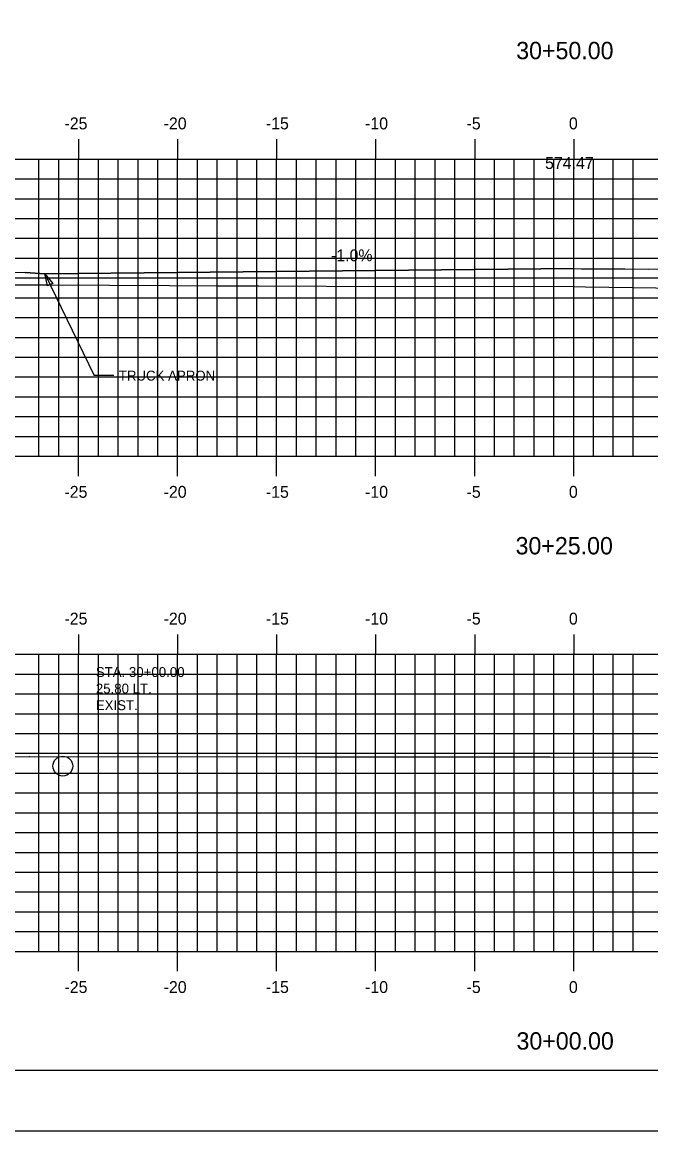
# Model space of a CAD drawing. Extents: x 1048109 to 1048279, y 781630 to 781740.
# Drawn here: x 1048163.9 to 1048195.6, y 781630.1 to 781686.1 of the extents above; entities that cross this region are included whole.
import ezdxf

# ---------------------------------------------------------------- set-up
doc = ezdxf.new("R2010")
doc.units = 0
for name, color, linetype in [('ANNOTATION', 7, 'Continuous'), ('D_Roadway_Centerline', 7, 'Continuous'), ('D_Roadway_Centerline_Text', 7, 'Continuous'), ('D_Text_Monospaced', 7, 'Continuous'), ('Default', 7, 'Continuous'), ('H_V ANNOTATION', 7, 'Continuous'), ('MAJOR', 7, 'Continuous'), ('MINOR', 7, 'Continuous'), ('S_Roadway_Centerline', 7, 'Continuous'), ('S_Utilities_UG_Water_Line', 7, 'Continuous')]:
    doc.layers.add(name, color=color, linetype=linetype)

msp = doc.modelspace()

# ---------------------------------------------------------------- linework, layer by layer
at = {"layer": 'ANNOTATION'}
for p in [(1048165.033, 781673.396), (1048168.514, 781668.263)]:
    msp.add_line(p, (1048167.514, 781668.263), dxfattribs=at)
msp.add_lwpolyline([(1048165.159, 781672.791), (1048165.033, 781673.396), (1048165.429, 781672.921)], close=True, dxfattribs=at)
at = {"layer": 'D_Roadway_Centerline'}
for p, q in [((1048145.246, 781673.605), (1048164.033, 781673.476)), ((1048165.033, 781673.396), (1048164.033, 781673.476)), ((1048191.733, 781673.663), (1048165.033, 781673.396)), ((1048191.733, 781673.663), (1048222.163, 781673.508))]:
    msp.add_line(p, q, dxfattribs=at)
msp.add_lwpolyline([(1048164.033, 781673.476), (1048165.033, 781673.396), (1048191.733, 781673.663), (1048192.119, 781673.655), (1048195.523, 781673.644)], dxfattribs=at)
at = {"layer": 'Default'}
msp.add_line((1048116.734, 781633.195), (1048276.734, 781633.195), dxfattribs=at)
msp.add_lwpolyline([(1048108.64, 781630.136), (1048278.64, 781630.136), (1048278.64, 781740.136), (1048108.64, 781740.136)], close=True, dxfattribs=at)
at = {"layer": 'MAJOR'}
for p, q in [((1048166.733, 781680.197), (1048166.733, 781679.195)), ((1048166.733, 781680.197), (1048166.733, 781679.195)), ((1048171.733, 781680.197), (1048171.733, 781679.195)), ((1048171.733, 781680.197), (1048171.733, 781679.195)), ((1048176.733, 781680.197), (1048176.733, 781679.195)), ((1048176.733, 781680.197), (1048176.733, 781679.195)), ((1048181.733, 781680.197), (1048181.733, 781679.195)), ((1048181.733, 781680.197), (1048181.733, 781679.195)), ((1048186.733, 781680.197), (1048186.733, 781679.195)), ((1048186.733, 781680.197), (1048186.733, 781679.195)), ((1048191.733, 781680.197), (1048191.733, 781679.195)), ((1048191.733, 781680.197), (1048191.733, 781679.195)), ((1048121.733, 781679.195), (1048261.733, 781679.195)), ((1048121.733, 781679.195), (1048261.733, 781679.195)), ((1048121.733, 781679.195), (1048261.733, 781679.195)), ((1048121.733, 781679.195), (1048261.733, 781679.195)), ((1048166.733, 781664.195), (1048166.733, 781679.195)), ((1048166.733, 781664.195), (1048166.733, 781679.195)), ((1048171.733, 781664.195), (1048171.733, 781679.195)), ((1048171.733, 781664.195), (1048171.733, 781679.195)), ((1048176.733, 781664.195), (1048176.733, 781679.195)), ((1048176.733, 781664.195), (1048176.733, 781679.195)), ((1048181.733, 781664.195), (1048181.733, 781679.195)), ((1048181.733, 781664.195), (1048181.733, 781679.195)), ((1048186.733, 781664.195), (1048186.733, 781679.195)), ((1048186.733, 781664.195), (1048186.733, 781679.195)), ((1048191.733, 781664.195), (1048191.733, 781679.195)), ((1048191.733, 781664.195), (1048191.733, 781679.195)), ((1048121.733, 781674.195), (1048261.733, 781674.195)), ((1048121.733, 781674.195), (1048261.733, 781674.195)), ((1048121.733, 781669.195), (1048261.733, 781669.195)), ((1048121.733, 781669.195), (1048261.733, 781669.195)), ((1048121.733, 781664.195), (1048261.733, 781664.195)), ((1048121.733, 781664.195), (1048261.733, 781664.195)), ((1048121.733, 781664.195), (1048261.733, 781664.195)), ((1048121.733, 781664.195), (1048261.733, 781664.195)), ((1048166.733, 781663.193), (1048166.733, 781664.195)), ((1048166.733, 781663.193), (1048166.733, 781664.195)), ((1048171.733, 781663.193), (1048171.733, 781664.195)), ((1048171.733, 781663.193), (1048171.733, 781664.195)), ((1048176.733, 781663.193), (1048176.733, 781664.195)), ((1048176.733, 781663.193), (1048176.733, 781664.195)), ((1048181.733, 781663.193), (1048181.733, 781664.195)), ((1048181.733, 781663.193), (1048181.733, 781664.195)), ((1048186.733, 781663.193), (1048186.733, 781664.195)), ((1048186.733, 781663.193), (1048186.733, 781664.195)), ((1048191.733, 781663.193), (1048191.733, 781664.195)), ((1048191.733, 781663.193), (1048191.733, 781664.195)), ((1048166.733, 781655.197), (1048166.733, 781654.195)), ((1048166.733, 781655.197), (1048166.733, 781654.195)), ((1048171.733, 781655.197), (1048171.733, 781654.195)), ((1048171.733, 781655.197), (1048171.733, 781654.195)), ((1048176.733, 781655.197), (1048176.733, 781654.195)), ((1048176.733, 781655.197), (1048176.733, 781654.195)), ((1048181.733, 781655.197), (1048181.733, 781654.195)), ((1048181.733, 781655.197), (1048181.733, 781654.195)), ((1048186.733, 781655.197), (1048186.733, 781654.195)), ((1048186.733, 781655.197), (1048186.733, 781654.195)), ((1048191.733, 781655.197), (1048191.733, 781654.195)), ((1048191.733, 781655.197), (1048191.733, 781654.195)), ((1048121.733, 781654.195), (1048261.733, 781654.195)), ((1048121.733, 781654.195), (1048261.733, 781654.195)), ((1048121.733, 781654.195), (1048261.733, 781654.195)), ((1048121.733, 781654.195), (1048261.733, 781654.195)), ((1048166.733, 781639.195), (1048166.733, 781654.195)), ((1048166.733, 781639.195), (1048166.733, 781654.195)), ((1048171.733, 781639.195), (1048171.733, 781654.195)), ((1048171.733, 781639.195), (1048171.733, 781654.195)), ((1048176.733, 781639.195), (1048176.733, 781654.195)), ((1048176.733, 781639.195), (1048176.733, 781654.195)), ((1048181.733, 781639.195), (1048181.733, 781654.195)), ((1048181.733, 781639.195), (1048181.733, 781654.195)), ((1048186.733, 781639.195), (1048186.733, 781654.195)), ((1048186.733, 781639.195), (1048186.733, 781654.195)), ((1048191.733, 781639.195), (1048191.733, 781654.195)), ((1048191.733, 781639.195), (1048191.733, 781654.195)), ((1048121.733, 781649.195), (1048261.733, 781649.195)), ((1048121.733, 781649.195), (1048261.733, 781649.195)), ((1048121.733, 781644.195), (1048261.733, 781644.195)), ((1048121.733, 781644.195), (1048261.733, 781644.195)), ((1048121.733, 781639.195), (1048261.733, 781639.195)), ((1048121.733, 781639.195), (1048261.733, 781639.195)), ((1048121.733, 781639.195), (1048261.733, 781639.195)), ((1048121.733, 781639.195), (1048261.733, 781639.195)), ((1048166.733, 781638.193), (1048166.733, 781639.195)), ((1048166.733, 781638.193), (1048166.733, 781639.195)), ((1048171.733, 781638.193), (1048171.733, 781639.195)), ((1048171.733, 781638.193), (1048171.733, 781639.195)), ((1048176.733, 781638.193), (1048176.733, 781639.195)), ((1048176.733, 781638.193), (1048176.733, 781639.195)), ((1048181.733, 781638.193), (1048181.733, 781639.195)), ((1048181.733, 781638.193), (1048181.733, 781639.195)), ((1048186.733, 781638.193), (1048186.733, 781639.195)), ((1048186.733, 781638.193), (1048186.733, 781639.195)), ((1048191.733, 781638.193), (1048191.733, 781639.195)), ((1048191.733, 781638.193), (1048191.733, 781639.195))]:
    msp.add_line(p, q, dxfattribs=at)
at = {"layer": 'MINOR'}
for p, q in [((1048164.733, 781664.195), (1048164.733, 781679.195)), ((1048164.733, 781664.195), (1048164.733, 781679.195)), ((1048165.733, 781664.195), (1048165.733, 781679.195)), ((1048165.733, 781664.195), (1048165.733, 781679.195)), ((1048167.733, 781664.195), (1048167.733, 781679.195)), ((1048167.733, 781664.195), (1048167.733, 781679.195)), ((1048168.733, 781664.195), (1048168.733, 781679.195)), ((1048168.733, 781664.195), (1048168.733, 781679.195)), ((1048169.733, 781664.195), (1048169.733, 781679.195)), ((1048169.733, 781664.195), (1048169.733, 781679.195)), ((1048170.733, 781664.195), (1048170.733, 781679.195)), ((1048170.733, 781664.195), (1048170.733, 781679.195)), ((1048172.733, 781664.195), (1048172.733, 781679.195)), ((1048172.733, 781664.195), (1048172.733, 781679.195)), ((1048173.733, 781664.195), (1048173.733, 781679.195)), ((1048173.733, 781664.195), (1048173.733, 781679.195)), ((1048174.733, 781664.195), (1048174.733, 781679.195)), ((1048174.733, 781664.195), (1048174.733, 781679.195)), ((1048175.733, 781664.195), (1048175.733, 781679.195)), ((1048175.733, 781664.195), (1048175.733, 781679.195)), ((1048177.733, 781664.195), (1048177.733, 781679.195)), ((1048177.733, 781664.195), (1048177.733, 781679.195)), ((1048178.733, 781664.195), (1048178.733, 781679.195)), ((1048178.733, 781664.195), (1048178.733, 781679.195)), ((1048179.733, 781664.195), (1048179.733, 781679.195)), ((1048179.733, 781664.195), (1048179.733, 781679.195)), ((1048180.733, 781664.195), (1048180.733, 781679.195)), ((1048180.733, 781664.195), (1048180.733, 781679.195)), ((1048182.733, 781664.195), (1048182.733, 781679.195)), ((1048182.733, 781664.195), (1048182.733, 781679.195)), ((1048183.733, 781664.195), (1048183.733, 781679.195)), ((1048183.733, 781664.195), (1048183.733, 781679.195)), ((1048184.733, 781664.195), (1048184.733, 781679.195)), ((1048184.733, 781664.195), (1048184.733, 781679.195)), ((1048185.733, 781664.195), (1048185.733, 781679.195)), ((1048185.733, 781664.195), (1048185.733, 781679.195)), ((1048187.733, 781664.195), (1048187.733, 781679.195)), ((1048187.733, 781664.195), (1048187.733, 781679.195)), ((1048188.733, 781664.195), (1048188.733, 781679.195)), ((1048188.733, 781664.195), (1048188.733, 781679.195)), ((1048189.733, 781664.195), (1048189.733, 781679.195)), ((1048189.733, 781664.195), (1048189.733, 781679.195)), ((1048190.733, 781664.195), (1048190.733, 781679.195)), ((1048190.733, 781664.195), (1048190.733, 781679.195)), ((1048192.733, 781664.195), (1048192.733, 781679.195)), ((1048192.733, 781664.195), (1048192.733, 781679.195)), ((1048193.733, 781664.195), (1048193.733, 781679.195)), ((1048193.733, 781664.195), (1048193.733, 781679.195)), ((1048194.733, 781664.195), (1048194.733, 781679.195)), ((1048194.733, 781664.195), (1048194.733, 781679.195)), ((1048121.733, 781678.195), (1048261.733, 781678.195)), ((1048121.733, 781678.195), (1048261.733, 781678.195)), ((1048121.733, 781677.195), (1048261.733, 781677.195)), ((1048121.733, 781677.195), (1048261.733, 781677.195)), ((1048121.733, 781676.195), (1048261.733, 781676.195)), ((1048121.733, 781676.195), (1048261.733, 781676.195)), ((1048121.733, 781675.195), (1048261.733, 781675.195)), ((1048121.733, 781675.195), (1048261.733, 781675.195)), ((1048121.733, 781673.195), (1048261.733, 781673.195)), ((1048121.733, 781673.195), (1048261.733, 781673.195)), ((1048121.733, 781672.195), (1048261.733, 781672.195)), ((1048121.733, 781672.195), (1048261.733, 781672.195)), ((1048121.733, 781671.195), (1048261.733, 781671.195)), ((1048121.733, 781671.195), (1048261.733, 781671.195)), ((1048121.733, 781670.195), (1048261.733, 781670.195)), ((1048121.733, 781670.195), (1048261.733, 781670.195)), ((1048121.733, 781668.195), (1048261.733, 781668.195)), ((1048121.733, 781668.195), (1048261.733, 781668.195)), ((1048121.733, 781667.195), (1048261.733, 781667.195)), ((1048121.733, 781667.195), (1048261.733, 781667.195)), ((1048121.733, 781666.195), (1048261.733, 781666.195)), ((1048121.733, 781666.195), (1048261.733, 781666.195)), ((1048121.733, 781665.195), (1048261.733, 781665.195)), ((1048121.733, 781665.195), (1048261.733, 781665.195)), ((1048164.733, 781639.195), (1048164.733, 781654.195)), ((1048164.733, 781639.195), (1048164.733, 781654.195)), ((1048165.733, 781639.195), (1048165.733, 781654.195)), ((1048165.733, 781639.195), (1048165.733, 781654.195)), ((1048167.733, 781639.195), (1048167.733, 781654.195)), ((1048167.733, 781639.195), (1048167.733, 781654.195)), ((1048168.733, 781639.195), (1048168.733, 781654.195)), ((1048168.733, 781639.195), (1048168.733, 781654.195)), ((1048169.733, 781639.195), (1048169.733, 781654.195)), ((1048169.733, 781639.195), (1048169.733, 781654.195)), ((1048170.733, 781639.195), (1048170.733, 781654.195)), ((1048170.733, 781639.195), (1048170.733, 781654.195)), ((1048172.733, 781639.195), (1048172.733, 781654.195)), ((1048172.733, 781639.195), (1048172.733, 781654.195)), ((1048173.733, 781639.195), (1048173.733, 781654.195)), ((1048173.733, 781639.195), (1048173.733, 781654.195)), ((1048174.733, 781639.195), (1048174.733, 781654.195)), ((1048174.733, 781639.195), (1048174.733, 781654.195)), ((1048175.733, 781639.195), (1048175.733, 781654.195)), ((1048175.733, 781639.195), (1048175.733, 781654.195)), ((1048177.733, 781639.195), (1048177.733, 781654.195)), ((1048177.733, 781639.195), (1048177.733, 781654.195)), ((1048178.733, 781639.195), (1048178.733, 781654.195)), ((1048178.733, 781639.195), (1048178.733, 781654.195)), ((1048179.733, 781639.195), (1048179.733, 781654.195)), ((1048179.733, 781639.195), (1048179.733, 781654.195)), ((1048180.733, 781639.195), (1048180.733, 781654.195)), ((1048180.733, 781639.195), (1048180.733, 781654.195)), ((1048182.733, 781639.195), (1048182.733, 781654.195)), ((1048182.733, 781639.195), (1048182.733, 781654.195)), ((1048183.733, 781639.195), (1048183.733, 781654.195)), ((1048183.733, 781639.195), (1048183.733, 781654.195)), ((1048184.733, 781639.195), (1048184.733, 781654.195)), ((1048184.733, 781639.195), (1048184.733, 781654.195)), ((1048185.733, 781639.195), (1048185.733, 781654.195)), ((1048185.733, 781639.195), (1048185.733, 781654.195)), ((1048187.733, 781639.195), (1048187.733, 781654.195)), ((1048187.733, 781639.195), (1048187.733, 781654.195)), ((1048188.733, 781639.195), (1048188.733, 781654.195)), ((1048188.733, 781639.195), (1048188.733, 781654.195)), ((1048189.733, 781639.195), (1048189.733, 781654.195)), ((1048189.733, 781639.195), (1048189.733, 781654.195)), ((1048190.733, 781639.195), (1048190.733, 781654.195)), ((1048190.733, 781639.195), (1048190.733, 781654.195)), ((1048192.733, 781639.195), (1048192.733, 781654.195)), ((1048192.733, 781639.195), (1048192.733, 781654.195)), ((1048193.733, 781639.195), (1048193.733, 781654.195)), ((1048193.733, 781639.195), (1048193.733, 781654.195)), ((1048194.733, 781639.195), (1048194.733, 781654.195)), ((1048194.733, 781639.195), (1048194.733, 781654.195)), ((1048121.733, 781653.195), (1048261.733, 781653.195)), ((1048121.733, 781653.195), (1048261.733, 781653.195)), ((1048121.733, 781652.195), (1048261.733, 781652.195)), ((1048121.733, 781652.195), (1048261.733, 781652.195)), ((1048121.733, 781651.195), (1048261.733, 781651.195)), ((1048121.733, 781651.195), (1048261.733, 781651.195)), ((1048121.733, 781650.195), (1048261.733, 781650.195)), ((1048121.733, 781650.195), (1048261.733, 781650.195)), ((1048121.733, 781648.195), (1048261.733, 781648.195)), ((1048121.733, 781648.195), (1048261.733, 781648.195)), ((1048121.733, 781647.195), (1048261.733, 781647.195)), ((1048121.733, 781647.195), (1048261.733, 781647.195)), ((1048121.733, 781646.195), (1048261.733, 781646.195)), ((1048121.733, 781646.195), (1048261.733, 781646.195)), ((1048121.733, 781645.195), (1048261.733, 781645.195)), ((1048121.733, 781645.195), (1048261.733, 781645.195)), ((1048121.733, 781643.195), (1048261.733, 781643.195)), ((1048121.733, 781643.195), (1048261.733, 781643.195)), ((1048121.733, 781642.195), (1048261.733, 781642.195)), ((1048121.733, 781642.195), (1048261.733, 781642.195)), ((1048121.733, 781641.195), (1048261.733, 781641.195)), ((1048121.733, 781641.195), (1048261.733, 781641.195)), ((1048121.733, 781640.195), (1048261.733, 781640.195)), ((1048121.733, 781640.195), (1048261.733, 781640.195))]:
    msp.add_line(p, q, dxfattribs=at)
at = {"layer": 'S_Roadway_Centerline'}
for points in [[(1048121.733, 781673.54), (1048124.021, 781673.514), (1048124.187, 781673.511), (1048124.678, 781673.501), (1048139.044, 781673.199), (1048143.343, 781673.047), (1048145.238, 781672.981), (1048146.562, 781672.932), (1048147.063, 781672.911), (1048147.593, 781672.904), (1048149.373, 781672.876), (1048151.33, 781672.839), (1048151.337, 781672.841), (1048165.263, 781672.839), (1048171.317, 781672.812), (1048173.701, 781672.801), (1048175.841, 781672.789), (1048179.234, 781672.771), (1048191.754, 781672.77), (1048192.331, 781672.75), (1048198.246, 781672.663), (1048213.646, 781672.566), (1048223.979, 781672.514)], [(1048191.754, 781672.77), (1048191.754, 781672.77)], [(1048121.733, 781648.883), (1048132.166, 781648.791), (1048158.795, 781649.038), (1048158.833, 781649.037), (1048162.032, 781649.025), (1048164.242, 781649.039), (1048164.257, 781649.038), (1048178.681, 781649.019), (1048190.522, 781649.013), (1048211.019, 781648.954), (1048233.093, 781648.88), (1048259.004, 781648.594), (1048261.733, 781648.51)]]:
    msp.add_lwpolyline(points, dxfattribs=at)
at = {"layer": 'S_Utilities_UG_Water_Line'}
msp.add_lwpolyline([(1048165.934, 781648.55), (1048165.94, 781648.55)], dxfattribs=at)
msp.add_circle((1048165.937, 781648.55), 0.501, dxfattribs=at)

# ---------------------------------------------------------------- texts
at = {"layer": 'ANNOTATION'}
msp.add_text('-1.0%', height=0.6, rotation=0.1474, dxfattribs=at).set_placement((1048179.479, 781674.032))
msp.add_text('TRUCK APRON', height=0.5, dxfattribs=at).set_placement((1048168.764, 781668.013))
at = {"layer": 'D_Roadway_Centerline_Text'}
msp.add_text('574.47', height=0.6, dxfattribs=at).set_placement((1048190.288, 781678.695))
at = {"layer": 'D_Text_Monospaced'}
for s, height, p in [('STA. 30+00.00', 0.49998, (1048167.604, 781653.048)), ('25.80 LT.', 0.5, (1048167.604, 781652.214)), ('EXIST. ', 0.5, (1048167.604, 781651.374))]:
    msp.add_text(s, height=height, dxfattribs=at).set_placement(p)
at = {"layer": 'H_V ANNOTATION'}
for s, height, p in [('30+50.00', 0.875, (1048188.831, 781684.238)), ('-25', 0.6, (1048166.019, 781680.695)), ('-20', 0.6, (1048171.027, 781680.695)), ('-15', 0.6, (1048176.19, 781680.695)), ('-10', 0.6, (1048181.198, 781680.695)), ('-5', 0.6, (1048186.324, 781680.695)), ('0', 0.6, (1048191.492, 781680.695)), ('-25', 0.6, (1048166.019, 781662.095)), ('-20', 0.6, (1048171.027, 781662.095)), ('-15', 0.6, (1048176.19, 781662.095)), ('-10', 0.6, (1048181.198, 781662.095)), ('-5', 0.6, (1048186.324, 781662.095)), ('0', 0.6, (1048191.492, 781662.095)), ('30+25.00', 0.875, (1048188.799, 781659.238)), ('-25', 0.6, (1048166.019, 781655.695)), ('-20', 0.6, (1048171.027, 781655.695)), ('-15', 0.6, (1048176.19, 781655.695)), ('-10', 0.6, (1048181.198, 781655.695)), ('-5', 0.6, (1048186.324, 781655.695)), ('0', 0.6, (1048191.492, 781655.695)), ('-25', 0.6, (1048166.019, 781637.095)), ('-20', 0.6, (1048171.027, 781637.095)), ('-15', 0.6, (1048176.19, 781637.095)), ('-10', 0.6, (1048181.198, 781637.095)), ('-5', 0.6, (1048186.324, 781637.095)), ('0', 0.6, (1048191.492, 781637.095)), ('30+00.00', 0.875, (1048188.846, 781634.238))]:
    msp.add_text(s, height=height, dxfattribs=at).set_placement(p)
at = {"layer": 'S_Roadway_Centerline'}
for s, p in [('C', (1048191.749, 781672.77)), ('L', (1048191.754, 781672.763))]:
    msp.add_text(s, height=0.0146, dxfattribs=at).set_placement(p)

doc.saveas('drawing.dxf')
